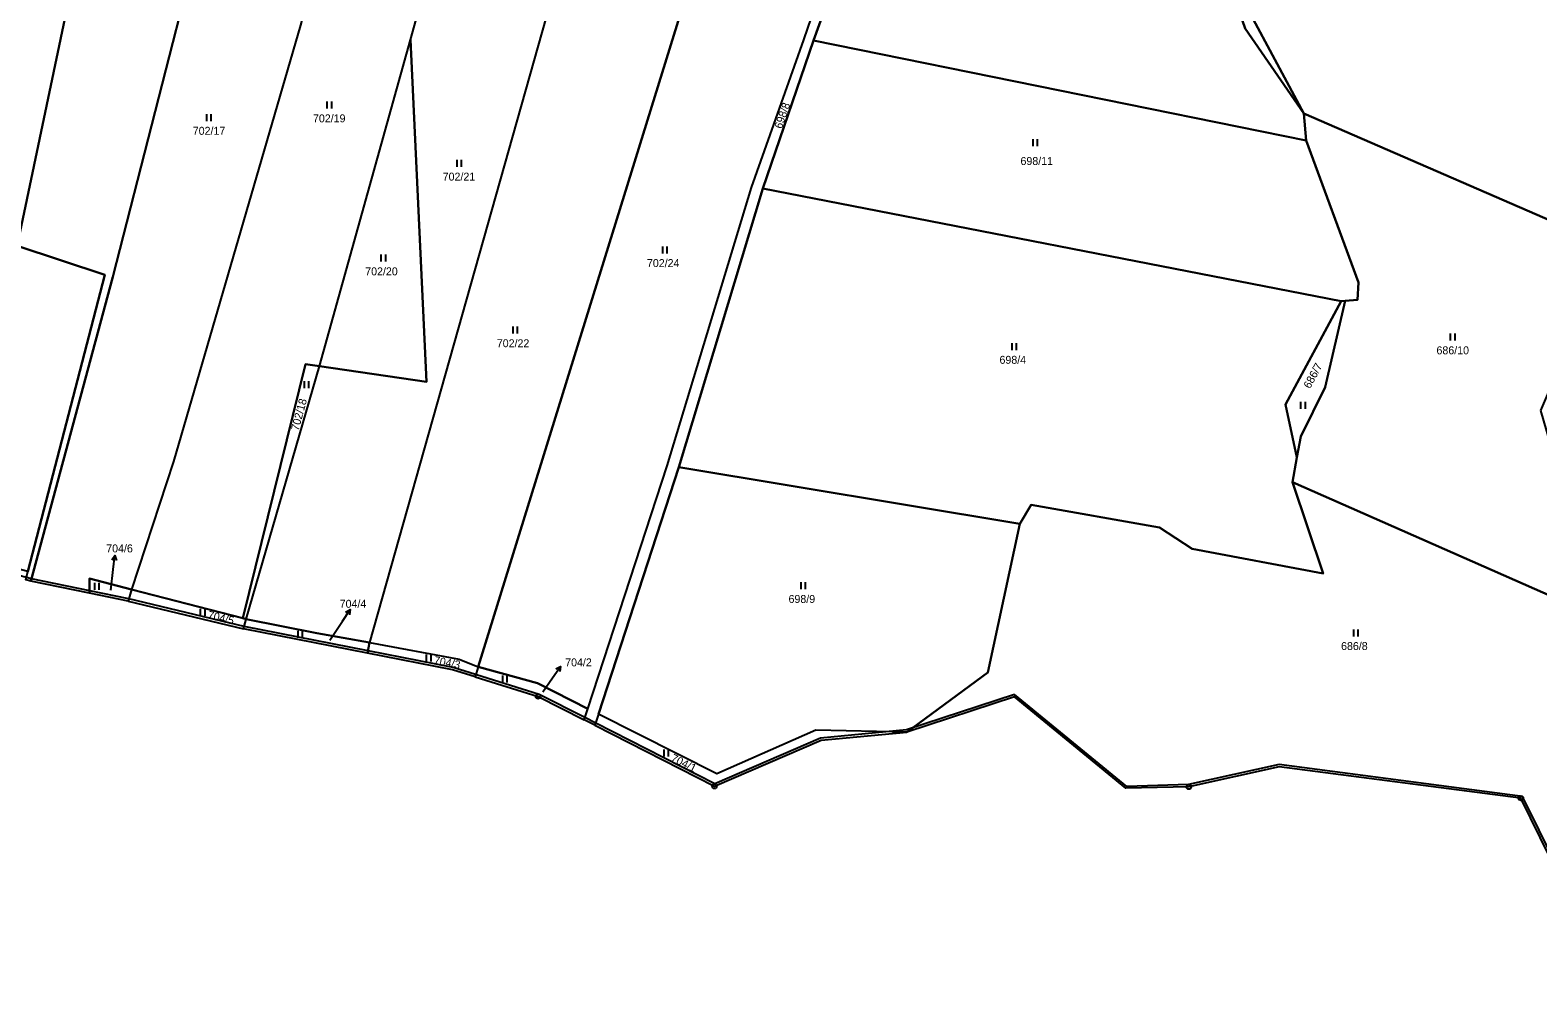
# Model space of a CAD drawing. Extents: x -654083 to -650132, y -1099819 to -1096699.
# Drawn here: x -652845.6 to -652523.2, y -1099272 to -1099068.9 of the extents above; entities that cross this region are included whole.
import ezdxf

# ---------------------------------------------------------------- set-up
doc = ezdxf.new("R2010")
doc.units = 0
for name, color, linetype in [('Geodetické body', 7, 'Continuous'), ('Obvody jako plochy', 7, 'Continuous'), ('Ostatní hranice', 7, 'Continuous'), ('Parcelní čísla', 7, 'Continuous'), ('Prvky pro prodl_ par_ č_', 7, 'Continuous'), ('Značky kultur', 7, 'Continuous')]:
    doc.layers.add(name, color=color, linetype=linetype)

msp = doc.modelspace()

# ---------------------------------------------------------------- linework, layer by layer
at = {"layer": 'Geodetické body'}
for centre, radius in [((-652736.99, -1099211.54), 0.5), ((-652736.99, -1099211.54), 0.001), ((-652699.26, -1099230.76), 0.5), ((-652699.26, -1099230.76), 0.001), ((-652597.86, -1099230.9), 0.5), ((-652597.86, -1099230.9), 0.001), ((-652526.81, -1099233.31), 0.5), ((-652526.81, -1099233.31), 0.001)]:
    msp.add_circle(centre, radius, dxfattribs=at)
at = {"layer": 'Obvody jako plochy'}
for points in [[(-652827.88, -1099121.75), (-652845.42, -1099186.87), (-652846.55, -1099186.57), (-652846.09, -1099184.77), (-652829.65, -1099121.29), (-652848.38, -1099115.11), (-652834.28, -1099047.75), (-652848.21, -1099036.14), (-652834.57, -1099009.35), (-652844.48, -1098996.43), (-652850.81, -1098995.64), (-652845.75, -1098972.4), (-652793.87, -1098980.22), (-652805.29, -1099029.68), (-652805.89, -1099020.61), (-652807.74, -1099014.47), (-652812.3, -1099013.77), (-652812.07, -1099008.28), (-652816.71, -1099007.93), (-652821.53, -1099045.3), (-652813.78, -1099051.69), (-652809.81, -1099050.94)], [(-652766.11, -1098984.41), (-652787.77, -1099067.92), (-652814.91, -1099161.23), (-652823.91, -1099188.64), (-652832.92, -1099186.32), (-652832.94, -1099189.44), (-652845.42, -1099186.87), (-652827.88, -1099121.75), (-652809.81, -1099050.94), (-652805.61, -1099050.02), (-652805.29, -1099029.68), (-652793.87, -1098980.22)], [(-652764.28, -1099071.04), (-652757.98, -1099048.43), (-652742.33, -1098992.01), (-652766.11, -1098984.41), (-652787.77, -1099067.92), (-652814.91, -1099161.23), (-652823.91, -1099188.64), (-652800.14, -1099194.77), (-652786.69, -1099140.42), (-652783.74, -1099140.87)], [(-652834.28, -1099047.75), (-652848.38, -1099115.11), (-652829.65, -1099121.29), (-652846.09, -1099184.77), (-652892.51, -1099172.5), (-652863.61, -1099053.36), (-652850.81, -1098995.64), (-652844.48, -1098996.43), (-652834.57, -1099009.35), (-652848.21, -1099036.14)], [(-652674.38, -1099000.48), (-652691.55, -1099039.51), (-652694.1, -1099038.56), (-652699.11, -1099049.36), (-652701.37, -1099048.77), (-652749.79, -1099205.17), (-652737.14, -1099208.72), (-652726.38, -1099214.16), (-652709.36, -1099162.16), (-652691.37, -1099102.65), (-652680.17, -1099070.99), (-652665.33, -1099027.7), (-652657.55, -1099002.94)], [(-652688.96, -1099102.81), (-652706.9, -1099162.49), (-652724.09, -1099215.32), (-652724.87, -1099217.71), (-652727.16, -1099216.54), (-652726.38, -1099214.16), (-652709.36, -1099162.16), (-652691.37, -1099102.65), (-652680.17, -1099070.99), (-652665.33, -1099027.7), (-652657.55, -1099002.94), (-652654.36, -1099001.13), (-652662.49, -1099027.9), (-652678.11, -1099071.15)], [(-652486.72, -1099066.1), (-652504.77, -1099092.04), (-652509.84, -1099106.19), (-652505.66, -1099110.73), (-652507.62, -1099115.29), (-652573.21, -1099086.81), (-652590.85, -1099053.87), (-652595.51, -1099042.32), (-652598.64, -1099030.86), (-652611.41, -1099027.66), (-652604.75, -1099007.48), (-652573.02, -1099023.24), (-652574, -1099031.22), (-652531.41, -1099043.9)], [(-652595.51, -1099042.32), (-652590.85, -1099053.87), (-652585.81, -1099068.6), (-652573.21, -1099086.81), (-652572.78, -1099092.57), (-652678.11, -1099071.15), (-652662.49, -1099027.9), (-652637.87, -1099035.68)], [(-652757.98, -1099048.43), (-652735, -1099037.22), (-652728.02, -1099040.33), (-652773, -1099200), (-652784.32, -1099198), (-652799.38, -1099194.97), (-652783.74, -1099140.87), (-652760.87, -1099144.21), (-652764.28, -1099071.04)], [(-652701.37, -1099048.77), (-652719.46, -1099043.83), (-652728.02, -1099040.33), (-652773, -1099200), (-652753.83, -1099203.59), (-652749.79, -1099205.17)], [(-652590.85, -1099053.87), (-652573.21, -1099086.81), (-652585.81, -1099068.6)], [(-652764.28, -1099071.04), (-652760.87, -1099144.21), (-652783.74, -1099140.87)], [(-652561.79, -1099126.66), (-652564.38, -1099126.87), (-652565.29, -1099126.95), (-652688.96, -1099102.81), (-652678.11, -1099071.15), (-652572.78, -1099092.57), (-652561.52, -1099122.92)], [(-652522.65, -1099150.36), (-652515.84, -1099173.67), (-652514.77, -1099178.52), (-652517.37, -1099185.51), (-652515.51, -1099192.22), (-652575.68, -1099165.7), (-652574.76, -1099160.43), (-652573.92, -1099155.92), (-652568.69, -1099145.34), (-652564.38, -1099126.87), (-652561.79, -1099126.66), (-652561.52, -1099122.92), (-652572.78, -1099092.57), (-652573.21, -1099086.81), (-652507.62, -1099115.29), (-652514.11, -1099130.38)], [(-652569.1, -1099185.2), (-652597.09, -1099179.93), (-652604.08, -1099175.4), (-652631.58, -1099170.53), (-652634, -1099174.58), (-652706.9, -1099162.49), (-652688.96, -1099102.81), (-652565.29, -1099126.95), (-652577.19, -1099149.04), (-652574.76, -1099160.43), (-652575.68, -1099165.7)], [(-652564.38, -1099126.87), (-652568.69, -1099145.34), (-652573.92, -1099155.92), (-652574.76, -1099160.43), (-652577.19, -1099149.04), (-652565.29, -1099126.95)], [(-652786.69, -1099140.42), (-652800.14, -1099194.77), (-652799.38, -1099194.97), (-652783.74, -1099140.87)], [(-652640.83, -1099206.43), (-652658.12, -1099219.17), (-652677.61, -1099218.75), (-652698.74, -1099228.09), (-652724.09, -1099215.32), (-652706.9, -1099162.49), (-652634, -1099174.58)], [(-652506.44, -1099213.13), (-652499.28, -1099223.01), (-652510.05, -1099271.98), (-652514.38, -1099258.69), (-652526.81, -1099233.31), (-652578.49, -1099226.63), (-652597.86, -1099230.9), (-652611.34, -1099231.19), (-652635.14, -1099211.6), (-652658.12, -1099219.17), (-652640.83, -1099206.43), (-652634, -1099174.58), (-652631.58, -1099170.53), (-652604.08, -1099175.4), (-652597.09, -1099179.93), (-652569.1, -1099185.2), (-652575.68, -1099165.7), (-652515.51, -1099192.22)], [(-652832.92, -1099186.32), (-652823.91, -1099188.64), (-652824.67, -1099191.15), (-652832.94, -1099189.44)], [(-652824.67, -1099191.15), (-652799.99, -1099197.05), (-652799.38, -1099194.97), (-652800.14, -1099194.77), (-652823.91, -1099188.64)], [(-652784.32, -1099198), (-652773, -1099200), (-652773.46, -1099202.26), (-652799.99, -1099197.05), (-652799.38, -1099194.97)], [(-652773, -1099200), (-652753.83, -1099203.59), (-652749.79, -1099205.17), (-652750.46, -1099207.34), (-652755.31, -1099205.83), (-652773.46, -1099202.26)], [(-652736.99, -1099211.54), (-652727.16, -1099216.54), (-652726.38, -1099214.16), (-652737.14, -1099208.72), (-652749.79, -1099205.17), (-652750.46, -1099207.34)], [(-652699.26, -1099230.76), (-652676.45, -1099220.93), (-652658.12, -1099219.17), (-652677.61, -1099218.75), (-652698.74, -1099228.09), (-652724.09, -1099215.32), (-652724.87, -1099217.71)]]:
    msp.add_lwpolyline(points, close=True, dxfattribs=at)
at = {"layer": 'Ostatní hranice'}
for p, q in [((-652845.29, -1099186.39), (-652892.85, -1099173.92)), ((-652832.83, -1099188.97), (-652845.29, -1099186.39)), ((-652824.52, -1099190.67), (-652832.83, -1099188.97)), ((-652799.84, -1099196.57), (-652824.52, -1099190.67)), ((-652773.34, -1099201.78), (-652799.84, -1099196.57)), ((-652755.17, -1099205.35), (-652773.34, -1099201.78)), ((-652736.75, -1099211.1), (-652755.17, -1099205.35)), ((-652727.01, -1099216.07), (-652736.75, -1099211.1)), ((-652635.08, -1099211.1), (-652658.21, -1099218.68)), ((-652611.06, -1099230.78), (-652635.08, -1099211.1)), ((-652724.67, -1099217.26), (-652727.01, -1099216.07)), ((-652699.21, -1099230.26), (-652724.67, -1099217.26)), ((-652658.21, -1099218.68), (-652676.61, -1099220.46)), ((-652676.61, -1099220.46), (-652699.21, -1099230.26)), ((-652578.52, -1099226.13), (-652597.92, -1099230.4)), ((-652526.46, -1099232.95), (-652578.52, -1099226.13)), ((-652597.92, -1099230.4), (-652611.06, -1099230.78)), ((-652513.91, -1099258.51), (-652526.46, -1099232.95))]:
    msp.add_line(p, q, dxfattribs=at)
at = {"layer": 'Prvky pro prodl_ par_ č_'}
for p, q in [((-652827.85, -1099184.37), (-652827.51, -1099181.39)), ((-652828.35, -1099188.77), (-652827.85, -1099184.37)), ((-652778.82, -1099195.43), (-652777.16, -1099192.93)), ((-652781.49, -1099199.47), (-652778.82, -1099195.43)), ((-652733.89, -1099207.57), (-652732.19, -1099205.1)), ((-652735.95, -1099210.58), (-652733.89, -1099207.57))]:
    msp.add_line(p, q, dxfattribs=at)
for points in [[(-652828.12, -1099182.33), (-652827.51, -1099181.39), (-652827.13, -1099182.44)], [(-652778.13, -1099193.49), (-652777.16, -1099192.93), (-652777.3, -1099194.04)], [(-652733.17, -1099205.64), (-652732.19, -1099205.1), (-652732.35, -1099206.2)]]:
    msp.add_lwpolyline(points, dxfattribs=at)
at = {"layer": 'Značky kultur'}
for p, q in [((-652807.89, -1099086.91), (-652807.89, -1099088.41)), ((-652806.86, -1099088.41), (-652806.86, -1099086.91)), ((-652782.15, -1099084.25), (-652782.15, -1099085.75)), ((-652781.12, -1099085.75), (-652781.12, -1099084.25)), ((-652631.18, -1099092.31), (-652631.18, -1099093.81)), ((-652630.16, -1099093.81), (-652630.16, -1099092.31)), ((-652754.35, -1099096.72), (-652754.35, -1099098.22)), ((-652753.33, -1099098.22), (-652753.33, -1099096.72)), ((-652710.38, -1099115.22), (-652710.38, -1099116.72)), ((-652709.35, -1099116.72), (-652709.35, -1099115.22)), ((-652770.59, -1099116.99), (-652770.59, -1099118.49)), ((-652769.57, -1099118.49), (-652769.57, -1099116.99)), ((-652742.41, -1099132.38), (-652742.41, -1099133.88)), ((-652741.39, -1099133.88), (-652741.39, -1099132.38)), ((-652541.92, -1099133.89), (-652541.92, -1099135.39)), ((-652540.9, -1099135.39), (-652540.9, -1099133.89)), ((-652635.69, -1099135.92), (-652635.69, -1099137.42)), ((-652634.67, -1099137.42), (-652634.67, -1099135.92)), ((-652787.02, -1099144.08), (-652787.02, -1099145.58)), ((-652785.99, -1099145.58), (-652785.99, -1099144.08)), ((-652573.94, -1099148.5), (-652573.94, -1099150)), ((-652572.92, -1099150), (-652572.92, -1099148.5)), ((-652680.79, -1099187.09), (-652680.79, -1099188.59)), ((-652679.77, -1099188.59), (-652679.77, -1099187.09)), ((-652831.84, -1099187.2), (-652831.84, -1099188.7)), ((-652830.82, -1099188.7), (-652830.82, -1099187.2)), ((-652809.22, -1099192.76), (-652809.22, -1099194.26)), ((-652808.2, -1099194.26), (-652808.2, -1099192.76)), ((-652788.37, -1099197.5), (-652788.37, -1099199)), ((-652787.34, -1099199), (-652787.34, -1099197.5)), ((-652562.62, -1099197.18), (-652562.62, -1099198.68)), ((-652561.59, -1099198.68), (-652561.59, -1099197.18)), ((-652760.88, -1099202.55), (-652760.88, -1099204.05)), ((-652759.85, -1099204.05), (-652759.85, -1099202.55)), ((-652744.59, -1099207.05), (-652744.59, -1099208.55)), ((-652743.57, -1099208.55), (-652743.57, -1099207.05)), ((-652710.12, -1099222.9), (-652710.12, -1099224.4)), ((-652709.09, -1099224.4), (-652709.09, -1099222.9))]:
    msp.add_line(p, q, dxfattribs=at)

# ---------------------------------------------------------------- texts
at = {"layer": 'Parcelní čísla'}
for s, p in [('702/19', (-652785.12, -1099088.68)), ('702/17', (-652810.82, -1099091.34)), ('698/11', (-652633.83, -1099097.81)), ('702/21', (-652757.38, -1099101.15)), ('702/24', (-652713.71, -1099119.65)), ('702/20', (-652773.95, -1099121.42)), ('702/22', (-652745.81, -1099136.81)), ('698/4', (-652638.32, -1099140.35)), ('686/10', (-652544.88, -1099138.32)), ('698/9', (-652683.43, -1099191.53)), ('686/8', (-652565.28, -1099201.61))]:
    msp.add_text(s, height=1.7, dxfattribs=at).set_placement(p)
for s, height, rotation, p in [('698/8', 1.7, 70.929, (-652684.9, -1099090.19)), ('686/7', 1.7, 61.713, (-652571.92, -1099145.8)), ('702/18', 1.7, 74.754, (-652788.21, -1099154.78)), ('704/6', 0.1, 347.022, (-652828.35, -1099188.77)), ('704/5', 1.7, 346.266, (-652807.75, -1099194.84)), ('704/4', 0.1, 349.758, (-652781.49, -1099199.47)), ('704/3', 1.7, 349.074, (-652759.38, -1099204.57)), ('704/2', 0.1, 342.774, (-652735.95, -1099210.58)), ('704/1', 1.7, 333.684, (-652708.75, -1099225.29))]:
    msp.add_text(s, height=height, rotation=rotation, dxfattribs=at).set_placement(p)
at = {"layer": 'Prvky pro prodl_ par_ č_'}
for s, p in [('704/6', (-652829.33, -1099180.71)), ('704/4', (-652779.41, -1099192.56)), ('704/2', (-652731.19, -1099205.1))]:
    msp.add_text(s, height=1.7, dxfattribs=at).set_placement(p)

doc.saveas('drawing.dxf')
